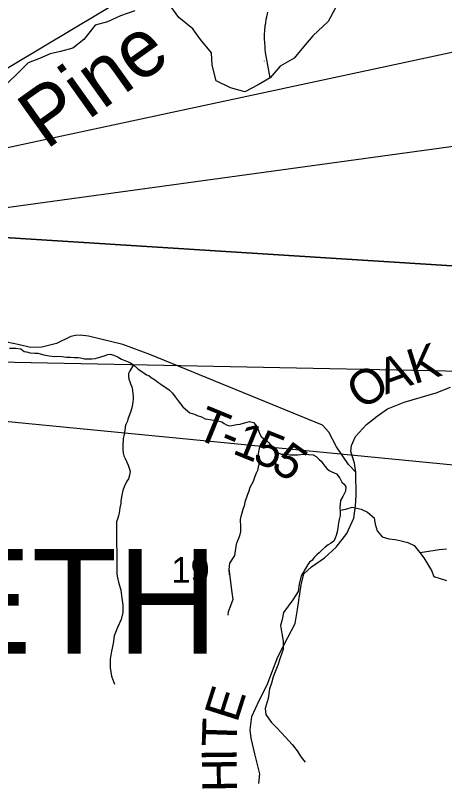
# Model space of a CAD drawing. Extents: x 0 to 44, y -23.8 to 22.
# Drawn here: x 6.622 to 7.321, y 16.572 to 17.815 of the extents above; entities that cross this region are included whole.
import ezdxf

# ---------------------------------------------------------------- set-up
doc = ezdxf.new("R2010")
doc.units = 0
for name, color, linetype in [('GM_X_County_Road', 7, 'Continuous'), ('GM_X_County_Road_Text', 7, 'Continuous'), ('GM_X_Minor_River', 7, 'Continuous'), ('GM_X_Minor_River_Text', 7, 'Continuous'), ('GM_X_Rail_Line', 7, 'Continuous'), ('GM_X_Section', 7, 'Continuous'), ('GM_X_Section_Text', 7, 'Continuous'), ('GM_X_Township_Road', 7, 'Continuous'), ('GM_X_Township_Road_Text', 7, 'Continuous'), ('GM_X_Township_Text', 7, 'Continuous'), ('SH_Data', 7, 'Continuous')]:
    doc.layers.add(name, color=color, linetype=linetype)

msp = doc.modelspace()

# ---------------------------------------------------------------- linework, layer by layer
at = {"layer": 'GM_X_County_Road'}
msp.add_lwpolyline([(7.0185, 16.5643), (7.0201, 16.5799), (7.012, 16.6122), (7.0065, 16.6377), (7.0047, 16.6513), (7.0075, 16.6734), (7.019, 16.6995), (7.0324, 16.7248), (7.0498, 16.7703), (7.0659, 16.8017), (7.0778, 16.8248), (7.0814, 16.8472), (7.0874, 16.8874), (7.0919, 16.9056), (7.1042, 16.9169), (7.1254, 16.9317), (7.1446, 16.9489), (7.1618, 16.9711), (7.1734, 16.9959), (7.1763, 17.0163), (7.1773, 17.0328), (7.1766, 17.0708), (7.1746, 17.0855), (7.1687, 17.1048), (7.1694, 17.1146), (7.1761, 17.1291), (7.1941, 17.1484), (7.2111, 17.1619), (7.2283, 17.174), (7.2551, 17.1851), (7.3076, 17.2002), (7.3307, 17.2091)], dxfattribs=at)
at = {"layer": 'GM_X_Minor_River'}
for points in [[(7.1437, 17.8267), (7.1314, 17.8048), (7.1066, 17.7814), (7.0913, 17.7632), (7.0764, 17.7447), (7.0536, 17.7319), (7.0372, 17.713), (7.0177, 17.7013), (6.9957, 17.69), (6.9726, 17.6966), (6.9495, 17.7081), (6.9425, 17.7336), (6.9419, 17.7537), (6.9238, 17.7751), (6.911, 17.7926), (6.8884, 17.811), (6.8752, 17.8289)], [(6.8168, 17.822), (6.7936, 17.8137), (6.7723, 17.804), (6.7522, 17.7984), (6.7338, 17.7753), (6.7159, 17.761), (6.6961, 17.7558), (6.679, 17.7521), (6.6616, 17.7442), (6.6433, 17.7371), (6.6227, 17.7167), (6.596, 17.6925)], [(7.0369, 17.7137), (7.0372, 17.713), (7.0295, 17.7539), (7.0292, 17.7596), (7.0292, 17.7645), (7.0285, 17.7687), (7.0278, 17.7775), (7.0279, 17.7847), (7.0284, 17.7888), (7.0292, 17.7983), (7.03, 17.8021), (7.0309, 17.8082), (7.032, 17.812), (7.0333, 17.8199)], [(7.0274, 17.7406), (7.0276, 17.7401)], [(6.6127, 17.2728), (6.6229, 17.2727), (6.6312, 17.2718), (6.6365, 17.2676), (6.6407, 17.2668), (6.6463, 17.2652), (6.6543, 17.2647), (6.6589, 17.2646), (6.663, 17.2638), (6.6687, 17.2622), (6.6774, 17.2602), (6.6865, 17.2594), (6.6903, 17.2597), (6.6983, 17.2592), (6.7055, 17.2584)], [(6.7055, 17.2584), (6.7123, 17.2579), (6.7183, 17.2578), (6.7244, 17.2574), (6.7282, 17.2569), (6.735, 17.2557), (6.7426, 17.2552), (6.7468, 17.2552), (6.7521, 17.2562), (6.7559, 17.257), (6.7601, 17.2584), (6.7688, 17.261), (6.773, 17.2624), (6.7768, 17.2628), (6.7825, 17.2612), (6.7897, 17.258), (6.7949, 17.2549), (6.8059, 17.2506), (6.81, 17.2487), (6.8146, 17.2456), (6.8225, 17.2386), (6.8285, 17.2351), (6.836, 17.2293), (6.8398, 17.2282), (6.8435, 17.2251), (6.8503, 17.2208), (6.8541, 17.2177), (6.859, 17.2142), (6.8646, 17.2104), (6.8691, 17.2076), (6.8729, 17.2049), (6.8782, 17.1996), (6.8823, 17.1934), (6.8875, 17.1869), (6.8912, 17.1823), (6.895, 17.1773), (6.8995, 17.1735), (6.9066, 17.1673), (6.9138, 17.1653), (6.9183, 17.1633), (6.9255, 17.161), (6.9315, 17.1578), (6.9357, 17.157), (6.9414, 17.1562), (6.9478, 17.1554), (6.9543, 17.1541), (6.9584, 17.1529), (6.9622, 17.1502), (6.966, 17.1479), (6.9705, 17.1463), (6.975, 17.1467), (6.983, 17.1485), (6.9883, 17.1491), (6.9952, 17.1513), (6.9998, 17.1524), (7.0036, 17.1535), (7.01, 17.1519), (7.016, 17.145), (7.0186, 17.137), (7.0204, 17.1328), (7.0226, 17.129), (7.0271, 17.1251), (7.0309, 17.1232), (7.0347, 17.1193), (7.038, 17.1147), (7.0418, 17.1105), (7.0455, 17.1055), (7.0493, 17.1028), (7.0549, 17.1004), (7.0614, 17.1), (7.0693, 17.0991), (7.0822, 17.0993), (7.0868, 17.0996), (7.091, 17.1), (7.0997, 17.0995), (7.1073, 17.099), (7.1122, 17.0963), (7.1167, 17.0917), (7.1204, 17.0886), (7.123, 17.0848), (7.126, 17.0805), (7.1294, 17.0767), (7.1332, 17.0736), (7.1377, 17.0717), (7.1415, 17.0701), (7.1452, 17.0681), (7.1508, 17.0612), (7.1538, 17.0547), (7.1576, 17.0513), (7.1602, 17.0471), (7.1597, 17.0402), (7.1554, 17.0315), (7.1516, 17.0251), (7.1507, 17.0134), (7.151, 17.0069), (7.1509, 17.0004), (7.1497, 16.994), (7.1485, 16.9887), (7.1473, 16.9796), (7.146, 16.9739), (7.1448, 16.9678)], [(6.8146, 17.2456), (6.8088, 17.2361), (6.8068, 17.2316), (6.8064, 17.2271), (6.8071, 17.2225), (6.8086, 17.2183), (6.81, 17.2145), (6.8119, 17.2099), (6.8129, 17.2042), (6.8136, 17.1985), (6.814, 17.1935), (6.8139, 17.1897), (6.8135, 17.1852), (6.8126, 17.1776), (6.8103, 17.17), (6.8083, 17.1643), (6.8052, 17.1575), (6.8048, 17.1538), (6.8021, 17.1485), (6.8013, 17.1447), (6.8004, 17.1386), (6.7988, 17.1303), (6.7976, 17.1257), (6.7976, 17.1212), (6.7972, 17.1174), (6.7971, 17.1128), (6.7974, 17.1079), (6.7981, 17.1018), (6.7992, 17.0976), (6.801, 17.093), (6.804, 17.0873), (6.8059, 17.0823), (6.8084, 17.0758), (6.8095, 17.072), (6.8083, 17.0663), (6.8067, 17.0599), (6.804, 17.0561), (6.8021, 17.0523), (6.7998, 17.0486), (6.7974, 17.041), (6.7962, 17.0361), (6.795, 17.0308), (6.7942, 17.024), (6.7938, 17.0202), (6.7925, 17.013), (6.7921, 17.0088), (6.7913, 17.005), (6.7901, 16.9997), (6.7893, 16.9959), (6.787, 16.9902), (6.7876, 16.9052)], [(7.0271, 17.1251), (7.0206, 17.1138), (7.019, 17.1089), (7.0182, 17.1047), (7.0178, 17.1001), (7.0177, 17.0937), (7.018, 17.0895), (7.0187, 17.0838), (7.0179, 17.0792), (7.0167, 17.0736), (7.0144, 17.0694), (7.0124, 17.0641), (7.0093, 17.0558), (7.0062, 17.0498), (7.0039, 17.046), (7.0023, 17.0399), (7.0003, 17.0346), (6.996, 17.0222), (6.9948, 17.0161), (6.9928, 17.0104), (6.9909, 17.0044), (6.9893, 16.9987), (6.9885, 16.9941), (6.9884, 16.9903), (6.9887, 16.9858), (6.989, 16.9797), (6.9886, 16.9744), (6.9874, 16.9675), (6.9854, 16.963), (6.9839, 16.9592), (6.9823, 16.9547), (6.9818, 16.9536)], [(7.1509, 17.0089), (7.1605, 17.0105), (7.1704, 17.0138), (7.1855, 17.0107), (7.1954, 17.0061), (7.2063, 16.9965), (7.2081, 16.9863), (7.2114, 16.9752), (7.2197, 16.9657), (7.2303, 16.9626), (7.2405, 16.9614), (7.2503, 16.9594), (7.2613, 16.9563), (7.2715, 16.9517), (7.2805, 16.941), (7.2873, 16.9315), (7.2932, 16.9216), (7.3, 16.9109), (7.3037, 16.901), (7.3048, 16.8999)], [(7.1448, 16.9678), (7.1429, 16.9633), (7.1406, 16.9584), (7.1352, 16.9547), (7.1314, 16.9524), (7.1268, 16.9487), (7.1218, 16.9446), (7.1172, 16.9397), (7.1134, 16.9363), (7.1088, 16.9318), (7.1049, 16.9269), (7.1011, 16.9243), (7.0984, 16.9206), (7.0977, 16.9196)], [(6.9818, 16.9536), (6.979, 16.9351), (6.971, 16.923), (6.9698, 16.9124), (6.9704, 16.9037)], [(7.2811, 16.9401), (7.2915, 16.9417), (7.3025, 16.9435), (7.3123, 16.945), (7.3241, 16.946)], [(7.0977, 16.9196), (7.0876, 16.9021), (7.0842, 16.8888), (7.0827, 16.8767), (7.0739, 16.8631), (7.0587, 16.8427), (7.0568, 16.8313), (7.0541, 16.8211), (7.056, 16.8085), (7.0582, 16.796), (7.0586, 16.7824), (7.0536, 16.7687), (7.0494, 16.757), (7.0418, 16.738), (7.0391, 16.7274), (7.0361, 16.718), (7.0338, 16.7024), (7.0292, 16.6865), (7.0299, 16.6766), (7.039, 16.6641), (7.048, 16.6546), (7.062, 16.6394), (7.0729, 16.6276), (7.0809, 16.6173), (7.0876, 16.607), (7.0944, 16.5987)], [(6.7876, 16.9052), (6.788, 16.9019), (6.7903, 16.8917), (6.7941, 16.8788), (6.7959, 16.8659), (6.7971, 16.8545), (6.7974, 16.8424), (6.7948, 16.831), (6.7887, 16.8181), (6.7831, 16.8044), (6.7816, 16.7923), (6.7789, 16.7798), (6.7766, 16.7665), (6.7766, 16.7525), (6.7789, 16.7388), (6.7838, 16.7256)], [(6.97, 16.9143), (6.9733, 16.8873), (6.9748, 16.8752), (6.9763, 16.8638), (6.9728, 16.8536), (6.9687, 16.8434), (6.9683, 16.838)], [(7.3037, 16.901), (7.3242, 16.8944)]]:
    msp.add_lwpolyline(points, dxfattribs=at)
at = {"layer": 'GM_X_Rail_Line'}
msp.add_lwpolyline([(7.045, 17.9889), (6.5222, 17.6767)], dxfattribs=at)
at = {"layer": 'GM_X_Section'}
for points in [[(6.5134, 18.488), (7.5123, 18.4238), (7.4446, 17.3999), (6.4419, 17.4633)], [(6.4419, 17.4633), (7.4446, 17.3999), (7.376, 16.3855), (6.3745, 16.447)]]:
    msp.add_lwpolyline(points, close=True, dxfattribs=at)
at = {"layer": 'GM_X_Township_Road'}
msp.add_lwpolyline([(7.1766, 17.0708), (7.1645, 17.0836), (7.1451, 17.1121), (7.1325, 17.136), (7.1224, 17.1476), (6.8411, 17.2624), (6.7974, 17.2786), (6.7416, 17.2922), (6.728, 17.2942), (6.7202, 17.2936), (6.7124, 17.2917), (6.6895, 17.2802), (6.6653, 17.2744), (6.6471, 17.2738), (6.629, 17.2783), (6.5981, 17.2847)], dxfattribs=at)
at = {"layer": 'SH_Data'}
for points in [[(5.3413, 17.3275), (9.7799, 18.2797), (9.7799, 17.9369)], [(5.3505, 17.2755), (9.7548, 17.1872), (9.7548, 16.8468)]]:
    msp.add_lwpolyline(points, close=True, dxfattribs=at)

# ---------------------------------------------------------------- texts
at = {"layer": 'GM_X_County_Road_Text'}
for s, rotation, p in [('K', 17.4149, (7.2712, 17.2137)), ('A', 19.8687, (7.2248, 17.1969)), ('O', 33.8093, (7.1865, 17.1708)), ('E', 72.3572, (6.9832, 16.6617)), ('T', 88.1311, (6.9825, 16.6232)), ('I', 90.6791, (6.9828, 16.6006)), ('H', 90.8561, (6.9835, 16.5506))]:
    msp.add_text(s, height=0.0568, rotation=rotation, dxfattribs=at).set_placement(p)
at = {"layer": 'GM_X_Minor_River_Text'}
msp.add_text('Pine', height=0.09469, rotation=35.4888, dxfattribs=at).set_placement((6.6723, 17.5948))
at = {"layer": 'GM_X_Section_Text'}
msp.add_text('19', height=0.04186, rotation=0, dxfattribs=at).set_placement((6.8764, 16.891))
at = {"layer": 'GM_X_Township_Road_Text'}
for s, rotation, p in [('T', 337.6801, (6.9127, 17.1272)), ('1', 337.829, (6.9738, 17.1022)), ('5', 338.3535, (7.0067, 17.0888)), ('-', 337.7059, (6.9521, 17.1111)), ('5', 324.5156, (7.0361, 17.0776))]:
    msp.add_text(s, height=0.0568, rotation=rotation, dxfattribs=at).set_placement(p)
at = {"layer": 'GM_X_Township_Text'}
msp.add_text('ELIZABETH', height=0.17045, rotation=0, dxfattribs=at).set_placement((5.7113, 16.7756))

doc.saveas('drawing.dxf')
